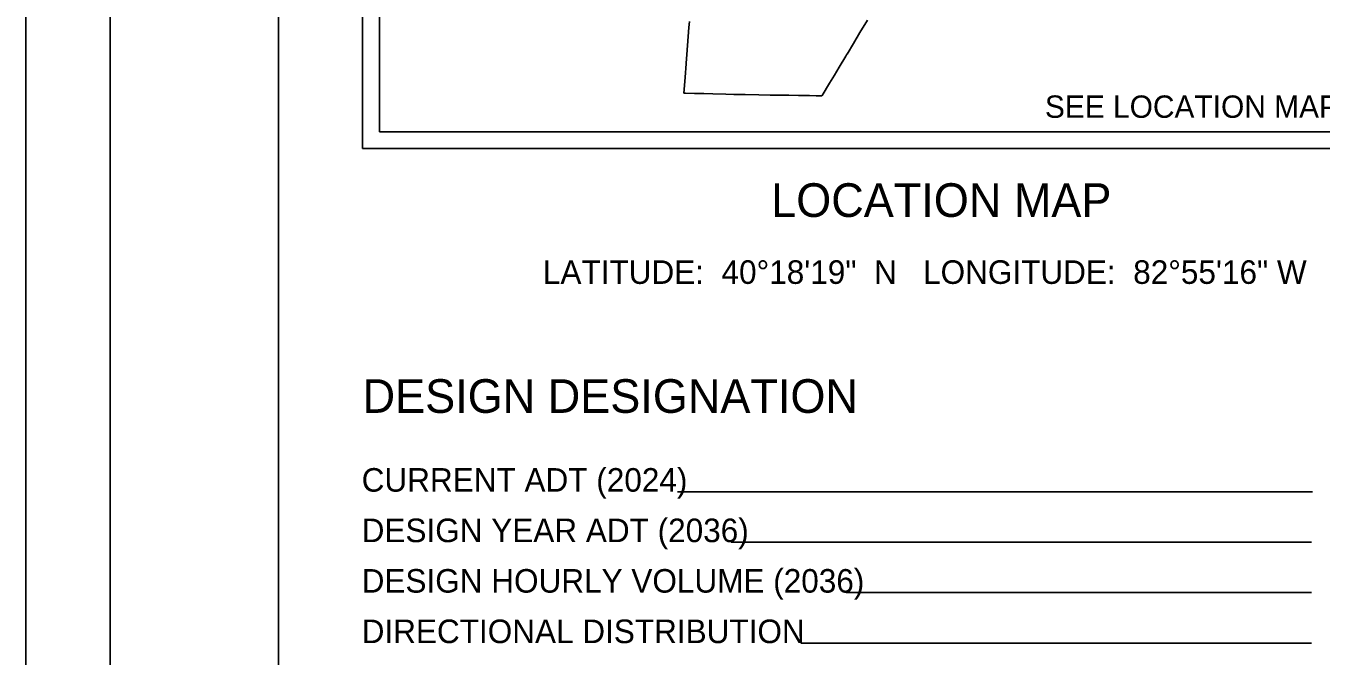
# Model space of a CAD drawing. Extents: x 0 to 34, y 0 to 22.
# Drawn here: x 0 to 7.69, y 10.98 to 14.73 of the extents above; entities that cross this region are included whole.
import ezdxf

# ---------------------------------------------------------------- set-up
doc = ezdxf.new("R2010")
doc.units = 0
for name, color, linetype in [('GM_X_County', 7, 'Continuous'), ('SH_Border', 7, 'Continuous'), ('SH_Cut_Line', 7, 'Continuous'), ('SH_Data', 7, 'Continuous'), ('SH_Text', 7, 'Continuous')]:
    doc.layers.add(name, color=color, linetype=linetype)

msp = doc.modelspace()

# ---------------------------------------------------------------- linework, layer by layer
at = {"layer": 'GM_X_County'}
for p, q in [((3.9258, 14.5598), (3.9382, 14.7199)), ((3.9382, 14.7199), (3.9409, 14.7543)), ((4.9988, 14.7636), (4.954, 14.6895)), ((4.9157, 14.6252), (4.8773, 14.5616)), ((4.954, 14.6895), (4.9157, 14.6252)), ((3.9217, 14.507), (3.9258, 14.5598)), ((4.8704, 14.5501), (4.8304, 14.4836)), ((4.8769, 14.5609), (4.8704, 14.5501)), ((4.877, 14.561), (4.8769, 14.5609)), ((4.8773, 14.5616), (4.877, 14.561)), ((3.9153, 14.4243), (3.9214, 14.5027)), ((3.9214, 14.5027), (3.9217, 14.507)), ((4.8304, 14.4836), (4.8021, 14.4367)), ((3.908, 14.3293), (3.9152, 14.4225)), ((3.9152, 14.4225), (3.9153, 14.4243)), ((4.7732, 14.3885), (4.7295, 14.3159)), ((4.8021, 14.4367), (4.7732, 14.3885)), ((3.9176, 14.3291), (3.908, 14.3293)), ((3.9723, 14.3278), (3.9176, 14.3291)), ((4.0264, 14.3264), (3.9723, 14.3278)), ((4.0813, 14.3251), (4.0264, 14.3264)), ((4.1576, 14.3232), (4.0813, 14.3251)), ((4.2041, 14.3221), (4.1576, 14.3232)), ((4.2443, 14.3211), (4.2041, 14.3221)), ((4.2497, 14.3209), (4.2443, 14.3211)), ((4.2723, 14.3206), (4.2497, 14.3209)), ((4.3539, 14.3194), (4.2723, 14.3206)), ((4.4199, 14.3184), (4.3539, 14.3194)), ((4.4969, 14.3173), (4.4199, 14.3184)), ((4.4986, 14.3173), (4.4969, 14.3173)), ((4.5316, 14.3168), (4.4986, 14.3173)), ((4.5893, 14.316), (4.5316, 14.3168)), ((4.6298, 14.3154), (4.5893, 14.316)), ((4.6547, 14.315), (4.6298, 14.3154)), ((4.6942, 14.3144), (4.6547, 14.315)), ((4.7193, 14.3141), (4.6942, 14.3144)), ((4.7283, 14.3139), (4.7193, 14.3141)), ((4.7295, 14.3159), (4.7283, 14.3139))]:
    msp.add_line(p, q, dxfattribs=at)
at = {"layer": 'SH_Border'}
for points in [[(0.5, 21.5), (1.5, 21.5), (1.5, 0.5), (0.5, 0.5)], [(1.5, 21.5), (33.5, 21.5), (33.5, 0.5), (1.5, 0.5)]]:
    msp.add_lwpolyline(points, close=True, dxfattribs=at)
at = {"layer": 'SH_Cut_Line'}
msp.add_lwpolyline([(0, 0), (34, 0), (34, 22), (0, 22)], close=True, dxfattribs=at)
at = {"layer": 'SH_Data'}
for p, q in [((2, 21), (2, 14)), ((2.1, 20.9), (2.1, 14.1)), ((2.1, 14.1), (8.9, 14.1)), ((2.1, 14.1), (2.1, 14.1)), ((2, 14), (9, 14)), ((7.6424, 11.9609), (3.871, 11.9609)), ((7.6368, 11.6609), (4.1885, 11.6609)), ((7.6368, 11.3609), (4.8723, 11.3609)), ((7.6368, 11.0609), (4.6037, 11.0609))]:
    msp.add_line(p, q, dxfattribs=at)

# ---------------------------------------------------------------- texts
for s, height, p in [('SEE LOCATION MAPS SHEETS 2-4', 0.132821, (6.0527, 14.1828)), ('DESIGN DESIGNATION', 0.2, (2, 12.4293))]:
    msp.add_text(s, height=height, dxfattribs=at).set_placement(p)
at = {"layer": 'SH_Text'}
for s, height, p in [('LOCATION MAP', 0.2, (4.4269, 13.5938)), ('LATITUDE:  40°18\'19"  N   LONGITUDE:  82°55\'16" W', 0.14, (3.071, 13.1959)), ('CURRENT ADT (2024)', 0.14, (1.9944, 11.9609)), ('DESIGN YEAR ADT (2036)', 0.14, (1.9944, 11.6609)), ('DESIGN HOURLY VOLUME (2036)', 0.14, (1.9944, 11.3609)), ('DIRECTIONAL DISTRIBUTION', 0.14, (1.9944, 11.0609))]:
    msp.add_text(s, height=height, dxfattribs=at).set_placement(p)

doc.saveas('drawing.dxf')
